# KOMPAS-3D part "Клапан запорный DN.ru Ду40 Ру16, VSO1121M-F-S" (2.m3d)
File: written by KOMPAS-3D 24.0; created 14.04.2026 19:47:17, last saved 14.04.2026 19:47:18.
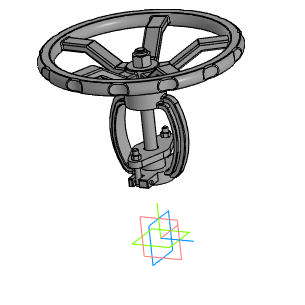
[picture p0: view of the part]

Document properties: Автор: R2D2; Полное имя файла: E:\Работа\Зайцев\VSO3131M-F-S Клапан запорный DN.ru Ду15-100 Ру40\DN40\исходные материалы\2.m3d

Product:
- Part/product: Клапан запорный DN.ru Ду40 Ру16  | designation VSO1121M-F-S
    Масса: 9.32
    Раздел спецификации: Прочие изделия
    Примечание: D090-01946

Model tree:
1. Операция без истории:1
2. Эскиз:1  (with: Ребро.Операция без истории:1)
3. Элемент вращения:1
     Угол 1 = 360
4. Эскиз:2  (with: Грань.Операция без истории:1, Ребро.Операция без истории:1)
5. Элемент выдавливания:1  (with: Грань.Операция без истории:1)
     Расстояние 1 = -27.625; Смещение 1 = 2; Расстояние 2 = -2

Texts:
  VSO1121M-F-S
